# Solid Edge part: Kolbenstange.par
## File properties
Author: ahadarics
Last saved by: ahadarics
Revision: 77
Sűrűség: 0,000 kg/m^3
Pontosság: 0,990
Username: ahadarics
Dokumentum tartalom típus: 0
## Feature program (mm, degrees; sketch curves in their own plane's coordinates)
base feature "unnamed BaseFeature 1"
thread "unnamed Thread 1"
chamfer "Letörés_1" setback 0.4
sketch for "Kihúzás_1" plane through (53.5, 0, 0) normal (1, 0, 0) x-axis (0, -1, 0)
  circle centre (0, 0) radius 8
extrude "Kihúzás_1" add finite 32 along -normal
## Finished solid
Body 1: solid body, 13 faces, 23 edges, 12 vertices.
  Faces by surface: plane 9, cylinder 3, cone 1
  Edges by curve: line 12, circle 11
Bounding box of the edges (mm): 105.500 x 16.000 x 16.000, from (-52, -8, -8) to (53.5, 8, 8).
Cylindrical faces by radius (mm): R3 x2, R8 x1
Conical faces (half-angle, radius in mm at the cone's reference point): 45 deg R2.6 x1
Planar faces by outward normal: +x 3, +z 1, -x 4, -z 1
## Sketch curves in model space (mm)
circle centre (53.5, 0, 0) radius 8
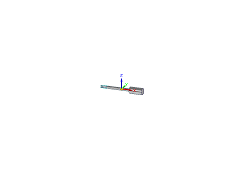
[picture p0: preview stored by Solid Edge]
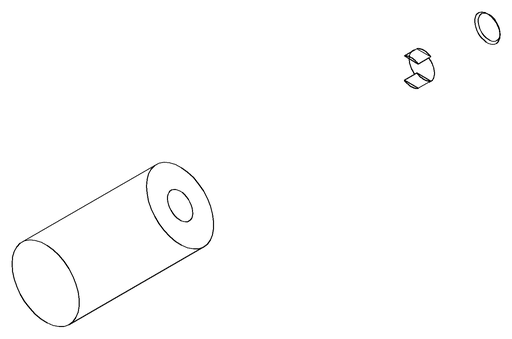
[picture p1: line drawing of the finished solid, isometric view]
